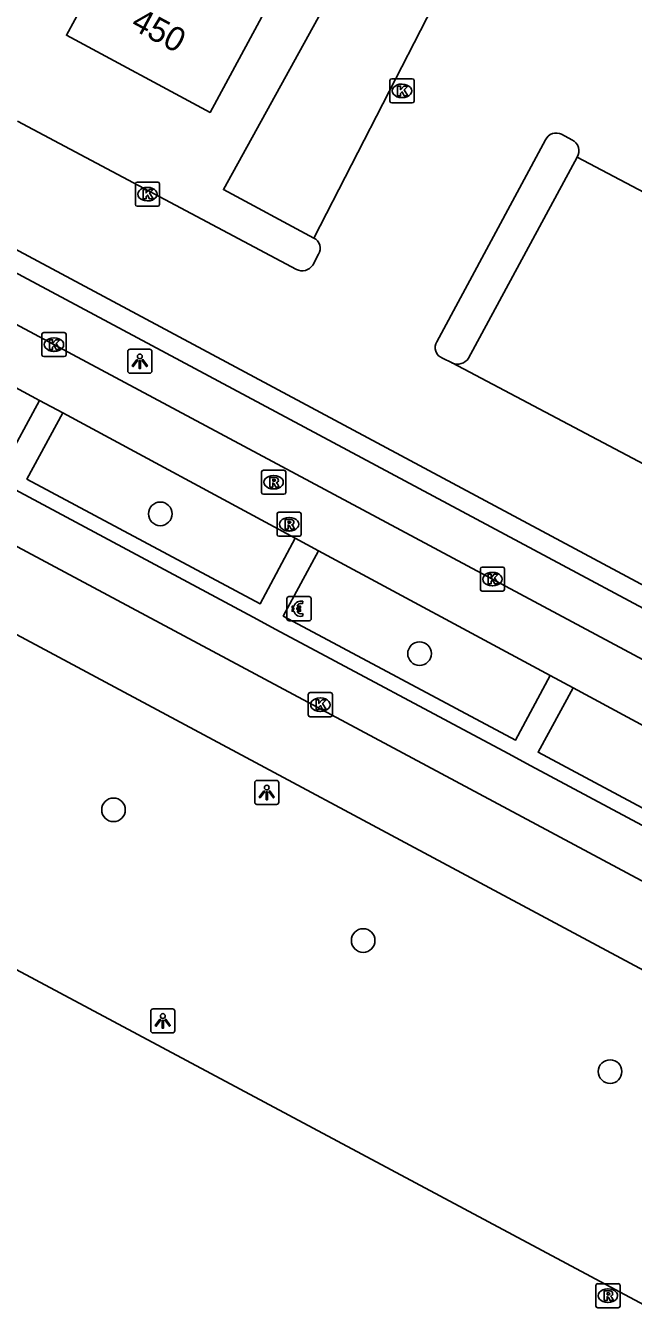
# Model space of a CAD drawing. Extents: x 159489 to 160304, y 383826 to 384530.
# Drawn here: x 159850 to 159875.2, y 383949.1 to 384002.3 of the extents above; entities that cross this region are included whole.
import ezdxf

# ---------------------------------------------------------------- set-up
doc = ezdxf.new("R2010")
doc.units = 0
for name, color, linetype in [('IMGEO_Betaalautomaat', 7, 'Continuous'), ('IMGEO_Boom', 7, 'Continuous'), ('IMGEO_Fietspad_gesloten', 7, 'Continuous'), ('IMGEO_Kolk', 7, 'Continuous'), ('IMGEO_Lichtpunt', 7, 'Continuous'), ('IMGEO_Pand', 7, 'Continuous'), ('IMGEO_Pand_nummerreeks', 7, 'Continuous'), ('IMGEO_Parkeervlak_open', 7, 'Continuous'), ('IMGEO_Rijbaan_lokaal_gesloten', 7, 'Continuous'), ('IMGEO_Rijbaan_lokaal_open', 7, 'Continuous'), ('IMGEO_Rioolput', 7, 'Continuous'), ('IMGEO_Voetpad_open', 7, 'Continuous')]:
    doc.layers.add(name, color=color, linetype=linetype)

msp = doc.modelspace()

# ---------------------------------------------------------------- linework, layer by layer
at = {"layer": 'IMGEO_Betaalautomaat'}
for p, q in [((159860.817, 383977.672), (159860.817, 383978.513)), ((159860.817, 383978.513), (159860.817, 383977.672)), ((159860.892, 383978.596), (159861.733, 383978.596)), ((159861.733, 383978.596), (159860.892, 383978.596)), ((159861.1, 383978.06), (159861.1, 383978.128)), ((159861.221, 383978.128), (159861.221, 383978.06)), ((159861.479, 383978.401), (159861.462, 383978.301)), ((159861.816, 383978.522), (159861.816, 383977.681)), ((159861.816, 383977.681), (159861.816, 383978.522)), ((159861.742, 383977.597), (159860.901, 383977.597)), ((159860.901, 383977.597), (159861.742, 383977.597)), ((159861.466, 383977.895), (159861.488, 383977.808))]:
    msp.add_line(p, q, dxfattribs=at)
for points in [[(159861.1, 383978.128), (159861.031, 383978.128), (159861.031, 383978.197), (159861.11, 383978.197)], [(159861.232, 383978.197), (159861.379, 383978.197), (159861.379, 383978.128), (159861.221, 383978.128)], [(159861.105, 383977.991), (159861.031, 383977.991), (159861.031, 383978.06), (159861.1, 383978.06)], [(159861.221, 383978.06), (159861.379, 383978.06), (159861.379, 383977.991), (159861.235, 383977.991)]]:
    msp.add_lwpolyline(points, dxfattribs=at)
for centre, radius, start, end in [((159860.895, 383978.519), 0.0779, 92.4484, 184.2845), ((159860.895, 383978.519), 0.0779, 92.4484, 184.2845), ((159861.393, 383978.121), 0.293, 73.014, 165.0139), ((159861.399, 383978.134), 0.179, 69.3236, 159.5683), ((159861.739, 383978.519), 0.0779, 2.4484, 94.2845), ((159861.739, 383978.519), 0.0779, 2.4484, 94.2845), ((159860.895, 383977.675), 0.0779, 182.4484, 274.2845), ((159860.895, 383977.675), 0.0779, 182.4484, 274.2845), ((159861.366, 383978.046), 0.267, 191.8096, 297.0389), ((159861.399, 383978.061), 0.179, 202.7625, 291.8693), ((159861.739, 383977.675), 0.0779, 272.4484, 4.2845), ((159861.739, 383977.675), 0.0779, 272.4484, 4.2845)]:
    msp.add_arc(centre, radius, start, end, dxfattribs=at)
at = {"layer": 'IMGEO_Boom'}
for centre in [(159855.571, 383982.025), (159866.307, 383976.234), (159853.632, 383969.76), (159863.972, 383964.345), (159874.198, 383958.915)]:
    msp.add_circle(centre, 0.489, dxfattribs=at)
at = {"layer": 'IMGEO_Fietspad_gesloten'}
for points in [[(159810.974, 384011.376), (159812.526, 384010.519), (159814.236, 384009.579), (159815.453, 384008.909), (159820.478, 384006.14), (159827.511, 384001.747), (159829.267, 384000.762), (159914.789, 383954.987)], [(159850.571, 383986.729), (159841.218, 383991.773)], [(159850.571, 383986.729), (159851.529, 383986.212)], [(159861.157, 383981.018), (159851.529, 383986.212)], [(159861.157, 383981.018), (159862.126, 383980.496)], [(159871.712, 383975.325), (159862.126, 383980.496)], [(159871.712, 383975.325), (159872.663, 383974.812)], [(159882.211, 383969.662), (159872.663, 383974.812)]]:
    msp.add_lwpolyline(points, dxfattribs=at)
at = {"layer": 'IMGEO_Kolk'}
for p, q in [((159865.079, 383999.128), (159865.079, 383999.98)), ((159865.154, 384000.054), (159866.006, 384000.054)), ((159866.08, 383999.98), (159866.08, 383999.128)), ((159865.567, 383999.834), (159865.592, 383999.834)), ((159866.006, 383999.054), (159865.154, 383999.054)), ((159865.59, 383999.274), (159865.565, 383999.274)), ((159854.537, 383994.847), (159854.537, 383995.699)), ((159854.612, 383995.773), (159855.464, 383995.773)), ((159855.538, 383995.699), (159855.538, 383994.847)), ((159855.025, 383995.553), (159855.05, 383995.553)), ((159855.464, 383994.773), (159854.612, 383994.773)), ((159855.048, 383994.993), (159855.023, 383994.993)), ((159850.667, 383988.614), (159850.667, 383989.466)), ((159850.742, 383989.54), (159851.594, 383989.54)), ((159851.155, 383989.32), (159851.18, 383989.32)), ((159851.668, 383989.466), (159851.668, 383988.614)), ((159851.178, 383988.76), (159851.153, 383988.76)), ((159851.594, 383988.54), (159850.742, 383988.54)), ((159868.825, 383978.895), (159868.825, 383979.747)), ((159868.9, 383979.821), (159869.752, 383979.821)), ((159869.826, 383979.747), (159869.826, 383978.895)), ((159869.313, 383979.601), (159869.338, 383979.601)), ((159869.752, 383978.821), (159868.9, 383978.821)), ((159869.336, 383979.041), (159869.311, 383979.041)), ((159861.698, 383973.691), (159861.698, 383974.543)), ((159861.773, 383974.617), (159862.625, 383974.617)), ((159862.699, 383974.543), (159862.699, 383973.691)), ((159862.186, 383974.397), (159862.211, 383974.397)), ((159862.625, 383973.617), (159861.773, 383973.617)), ((159862.209, 383973.837), (159862.184, 383973.837))]:
    msp.add_line(p, q, dxfattribs=at)
for points in [[(159865.079, 383999.128), (159865.079, 383999.98)], [(159865.154, 384000.054), (159866.006, 384000.054)], [(159866.08, 383999.98), (159866.08, 383999.128)], [(159865.4, 383999.754), (159865.523, 383999.754), (159865.523, 383999.603), (159865.653, 383999.754), (159865.817, 383999.754), (159865.671, 383999.603), (159865.824, 383999.354), (159865.672, 383999.354), (159865.587, 383999.518), (159865.523, 383999.451), (159865.523, 383999.354), (159865.4, 383999.354), (159865.4, 383999.754)], [(159866.006, 383999.054), (159865.154, 383999.054)], [(159854.537, 383994.847), (159854.537, 383995.699)], [(159854.612, 383995.773), (159855.464, 383995.773)], [(159855.538, 383995.699), (159855.538, 383994.847)], [(159854.858, 383995.473), (159854.981, 383995.473), (159854.981, 383995.322), (159855.111, 383995.473), (159855.275, 383995.473), (159855.129, 383995.322), (159855.282, 383995.073), (159855.13, 383995.073), (159855.045, 383995.237), (159854.981, 383995.17), (159854.981, 383995.073), (159854.858, 383995.073), (159854.858, 383995.473)], [(159855.464, 383994.773), (159854.612, 383994.773)], [(159850.667, 383988.614), (159850.667, 383989.466)], [(159850.742, 383989.54), (159851.594, 383989.54)], [(159851.668, 383989.466), (159851.668, 383988.614)], [(159850.988, 383989.24), (159851.111, 383989.24), (159851.111, 383989.089), (159851.241, 383989.24), (159851.405, 383989.24), (159851.259, 383989.089), (159851.412, 383988.84), (159851.26, 383988.84), (159851.175, 383989.004), (159851.111, 383988.937), (159851.111, 383988.84), (159850.988, 383988.84), (159850.988, 383989.24)], [(159851.594, 383988.54), (159850.742, 383988.54)], [(159868.825, 383978.895), (159868.825, 383979.747)], [(159868.9, 383979.821), (159869.752, 383979.821)], [(159869.826, 383979.747), (159869.826, 383978.895)], [(159869.146, 383979.521), (159869.269, 383979.521), (159869.269, 383979.37), (159869.399, 383979.521), (159869.563, 383979.521), (159869.417, 383979.37), (159869.57, 383979.121), (159869.418, 383979.121), (159869.333, 383979.285), (159869.269, 383979.218), (159869.269, 383979.121), (159869.146, 383979.121), (159869.146, 383979.521)], [(159869.752, 383978.821), (159868.9, 383978.821)], [(159861.698, 383973.691), (159861.698, 383974.543)], [(159861.773, 383974.617), (159862.625, 383974.617)], [(159862.699, 383974.543), (159862.699, 383973.691)], [(159862.019, 383974.317), (159862.142, 383974.317), (159862.142, 383974.166), (159862.272, 383974.317), (159862.436, 383974.317), (159862.29, 383974.166), (159862.443, 383973.917), (159862.291, 383973.917), (159862.206, 383974.081), (159862.142, 383974.014), (159862.142, 383973.917), (159862.019, 383973.917), (159862.019, 383974.317)], [(159862.625, 383973.617), (159861.773, 383973.617)]]:
    msp.add_lwpolyline(points, dxfattribs=at)
for centre, start, end in [((159865.156, 383999.978), 91.552, 178.448), ((159865.156, 383999.978), 91.552, 178.448), ((159866.004, 383999.978), 1.552, 88.448), ((159866.004, 383999.978), 1.552, 88.448), ((159865.156, 383999.13), 181.552, 268.448), ((159865.156, 383999.13), 181.552, 268.448), ((159866.004, 383999.13), 271.552, 358.448), ((159866.004, 383999.13), 271.552, 358.448), ((159854.614, 383995.697), 91.552, 178.448), ((159854.614, 383995.697), 91.552, 178.448), ((159855.462, 383995.697), 1.552, 88.448), ((159855.462, 383995.697), 1.552, 88.448), ((159854.614, 383994.849), 181.552, 268.448), ((159854.614, 383994.849), 181.552, 268.448), ((159855.462, 383994.849), 271.552, 358.448), ((159855.462, 383994.849), 271.552, 358.448), ((159850.744, 383989.464), 91.552, 178.448), ((159850.744, 383989.464), 91.552, 178.448), ((159851.592, 383989.464), 1.552, 88.448), ((159851.592, 383989.464), 1.552, 88.448), ((159850.744, 383988.616), 181.552, 268.448), ((159850.744, 383988.616), 181.552, 268.448), ((159851.592, 383988.616), 271.552, 358.448), ((159851.592, 383988.616), 271.552, 358.448), ((159868.902, 383979.745), 91.552, 178.448), ((159868.902, 383979.745), 91.552, 178.448), ((159869.75, 383979.745), 1.552, 88.448), ((159869.75, 383979.745), 1.552, 88.448), ((159868.902, 383978.897), 181.552, 268.448), ((159868.902, 383978.897), 181.552, 268.448), ((159869.75, 383978.897), 271.552, 358.448), ((159869.75, 383978.897), 271.552, 358.448), ((159861.775, 383974.541), 91.552, 178.448), ((159861.775, 383974.541), 91.552, 178.448), ((159862.623, 383974.541), 1.552, 88.448), ((159862.623, 383974.541), 1.552, 88.448), ((159861.775, 383973.693), 181.552, 268.448), ((159861.775, 383973.693), 181.552, 268.448), ((159862.623, 383973.693), 271.552, 358.448), ((159862.623, 383973.693), 271.552, 358.448)]:
    msp.add_arc(centre, 0.0765, start, end, dxfattribs=at)
for centre, major_axis, ratio, start_param, end_param in [((159865.566, 383999.554), (-0.387, 0.002), 0.722429, 4.712389, 7.853982), ((159865.591, 383999.554), (-0.39, 0.002), 0.717154, 1.570796, 4.712389), ((159855.024, 383995.273), (-0.387, 0.002), 0.722429, 4.712389, 7.853982), ((159855.049, 383995.273), (-0.39, 0.002), 0.717154, 1.570796, 4.712389), ((159851.154, 383989.04), (-0.387, 0.002), 0.722429, 4.712389, 7.853982), ((159851.179, 383989.04), (-0.39, 0.002), 0.717154, 1.570796, 4.712389), ((159869.312, 383979.321), (-0.387, 0.002), 0.722429, 4.712389, 7.853982), ((159869.337, 383979.321), (-0.39, 0.002), 0.717154, 1.570796, 4.712389), ((159862.185, 383974.117), (-0.387, 0.002), 0.722429, 4.712389, 7.853982), ((159862.21, 383974.117), (-0.39, 0.002), 0.717154, 1.570796, 4.712389)]:
    msp.add_ellipse(centre, major_axis=major_axis, ratio=ratio, start_param=start_param, end_param=end_param, dxfattribs=at)
at = {"layer": 'IMGEO_Lichtpunt'}
for p, q in [((159855.127, 383988.847), (159854.319, 383988.847)), ((159855.127, 383988.847), (159854.319, 383988.847)), ((159854.225, 383988.752), (159854.225, 383987.945)), ((159854.225, 383988.752), (159854.225, 383987.945)), ((159855.221, 383987.945), (159855.221, 383988.752)), ((159855.221, 383987.945), (159855.221, 383988.752)), ((159854.319, 383987.851), (159855.127, 383987.851)), ((159854.319, 383987.851), (159855.127, 383987.851)), ((159859.481, 383970.885), (159859.481, 383970.078)), ((159859.481, 383970.885), (159859.481, 383970.078)), ((159860.383, 383970.98), (159859.575, 383970.98)), ((159860.383, 383970.98), (159859.575, 383970.98)), ((159860.477, 383970.078), (159860.477, 383970.885)), ((159860.477, 383970.078), (159860.477, 383970.885)), ((159859.575, 383969.984), (159860.383, 383969.984)), ((159859.575, 383969.984), (159860.383, 383969.984)), ((159855.175, 383961.418), (159855.175, 383960.611)), ((159855.175, 383961.418), (159855.175, 383960.611)), ((159856.077, 383961.513), (159855.269, 383961.513)), ((159856.077, 383961.513), (159855.269, 383961.513)), ((159856.171, 383960.611), (159856.171, 383961.418)), ((159856.171, 383960.611), (159856.171, 383961.418)), ((159855.269, 383960.517), (159856.077, 383960.517)), ((159855.269, 383960.517), (159856.077, 383960.517))]:
    msp.add_line(p, q, dxfattribs=at)
for points in [[(159854.599, 383988.416), (159854.638, 383988.388), (159854.45, 383988.126), (159854.412, 383988.153), (159854.599, 383988.416)], [(159854.701, 383988.368), (159854.748, 383988.368), (159854.748, 383988.046), (159854.701, 383988.046), (159854.701, 383988.368)], [(159854.811, 383988.388), (159854.849, 383988.415), (159855.036, 383988.153), (159854.997, 383988.125), (159854.811, 383988.388)], [(159859.855, 383970.549), (159859.894, 383970.521), (159859.706, 383970.259), (159859.668, 383970.286), (159859.855, 383970.549)], [(159859.957, 383970.501), (159860.004, 383970.501), (159860.004, 383970.179), (159859.957, 383970.179), (159859.957, 383970.501)], [(159860.067, 383970.521), (159860.105, 383970.548), (159860.292, 383970.286), (159860.253, 383970.258), (159860.067, 383970.521)], [(159855.549, 383961.082), (159855.588, 383961.054), (159855.4, 383960.792), (159855.362, 383960.819), (159855.549, 383961.082)], [(159855.651, 383961.034), (159855.698, 383961.034), (159855.698, 383960.712), (159855.651, 383960.712), (159855.651, 383961.034)], [(159855.761, 383961.054), (159855.799, 383961.081), (159855.986, 383960.819), (159855.947, 383960.791), (159855.761, 383961.054)]]:
    msp.add_lwpolyline(points, dxfattribs=at)
for centre in [(159854.724, 383988.55), (159859.98, 383970.683), (159855.674, 383961.216)]:
    msp.add_circle(centre, 0.0994, dxfattribs=at)
for centre, start, end in [((159854.319, 383988.752), 90, 180), ((159854.319, 383988.752), 90, 180), ((159855.127, 383988.752), 0, 90), ((159855.127, 383988.752), 0, 90), ((159854.319, 383987.945), 180, 270), ((159854.319, 383987.945), 180, 270), ((159855.127, 383987.945), 270, 0), ((159855.127, 383987.945), 270, 360), ((159859.575, 383970.885), 90, 180), ((159859.575, 383970.885), 90, 180), ((159860.383, 383970.885), 0, 90), ((159860.383, 383970.885), 0, 90), ((159859.575, 383970.078), 180, 270), ((159859.575, 383970.078), 180, 270), ((159860.383, 383970.078), 270, 0), ((159860.383, 383970.078), 270, 360), ((159855.269, 383961.418), 90, 180), ((159855.269, 383961.418), 90, 180), ((159856.077, 383961.418), 0, 90), ((159856.077, 383961.418), 0, 90), ((159855.269, 383960.611), 180, 270), ((159855.269, 383960.611), 180, 270), ((159856.077, 383960.611), 270, 0), ((159856.077, 383960.611), 270, 360)]:
    msp.add_arc(centre, 0.0946, start, end, dxfattribs=at)
at = {"layer": 'IMGEO_Pand'}
msp.add_lwpolyline([(159861.9, 384006.569), (159855.968, 384009.769), (159854.991, 384007.958), (159853.233, 384008.905), (159850.977, 384004.724), (159852.72, 384003.785), (159851.682, 384001.859), (159857.633, 383998.662), (159861.9, 384006.569)], dxfattribs=at)
at = {"layer": 'IMGEO_Parkeervlak_open'}
msp.add_lwpolyline([(159868.337, 383988.475), (159872.835, 383996.806)], dxfattribs=at)
msp.add_arc((159867.88, 383988.774), 0.546, 245.5973, 326.7811, dxfattribs=at)
at = {"layer": 'IMGEO_Rijbaan_lokaal_gesloten'}
for points in [[(159888.304, 383959.967), (159818.858, 383997.143)], [(159840.297, 383982.009), (159884.338, 383958.42), (159887.722, 383956.4), (159898.39, 383949.315)], [(159893.167, 383939.859), (159842.117, 383967.14), (159837.777, 383969.747)]]:
    msp.add_lwpolyline(points, dxfattribs=at)
at = {"layer": 'IMGEO_Rijbaan_lokaal_open'}
for points in [[(159868.17, 384005.614), (159861.931, 383993.454)], [(159849.659, 383998.303), (159861.206, 383992.151)], [(159871.521, 383997.524), (159867.028, 383989.16)], [(159872.613, 383997.519), (159872.192, 383997.754)], [(159872.835, 383996.806), (159906.443, 383979.069)], [(159910.232, 383960.503), (159906.502, 383962.5), (159847.363, 383994.162)], [(159861.885, 383992.333), (159862.126, 383992.78)], [(159867.258, 383988.481), (159867.655, 383988.277)], [(159902.095, 383970.059), (159867.655, 383988.277)]]:
    msp.add_lwpolyline(points, dxfattribs=at)
for centre, radius, start, end in [((159871.968, 383997.313), 0.494, 63.0548, 154.7858), ((159872.415, 383997.066), 0.494, 328.1716, 66.4175), ((159861.73, 383993.031), 0.469, 327.7103, 64.5619), ((159861.44, 383992.637), 0.539, 244.302, 325.7079), ((159867.407, 383988.91), 0.454, 146.5775, 250.8484)]:
    msp.add_arc(centre, radius, start, end, dxfattribs=at)
at = {"layer": 'IMGEO_Rioolput'}
for p, q in [((159859.764, 383982.911), (159859.764, 383983.763)), ((159859.839, 383983.837), (159860.691, 383983.837)), ((159860.252, 383983.617), (159860.277, 383983.617)), ((159860.765, 383983.763), (159860.765, 383982.911)), ((159860.275, 383983.057), (159860.25, 383983.057)), ((159860.691, 383982.837), (159859.839, 383982.837)), ((159860.404, 383981.169), (159860.404, 383982.021)), ((159860.479, 383982.095), (159861.331, 383982.095)), ((159860.892, 383981.875), (159860.917, 383981.875)), ((159861.405, 383982.021), (159861.405, 383981.169)), ((159860.915, 383981.315), (159860.89, 383981.315)), ((159861.331, 383981.095), (159860.479, 383981.095)), ((159873.609, 383949.2), (159873.609, 383950.052)), ((159873.684, 383950.126), (159874.536, 383950.126)), ((159874.61, 383950.052), (159874.61, 383949.2)), ((159874.097, 383949.906), (159874.122, 383949.906)), ((159874.536, 383949.126), (159873.684, 383949.126)), ((159874.12, 383949.346), (159874.095, 383949.346))]:
    msp.add_line(p, q, dxfattribs=at)
for points in [[(159859.764, 383982.911), (159859.764, 383983.763)], [(159859.839, 383983.837), (159860.691, 383983.837)], [(159860.353, 383983.535), (159860.101, 383983.537), (159860.101, 383983.137)], [(159860.279, 383983.456), (159860.225, 383983.456), (159860.225, 383983.375)], [(159860.765, 383983.763), (159860.765, 383982.911)], [(159860.101, 383983.137), (159860.225, 383983.137), (159860.225, 383983.299), (159860.236, 383983.299)], [(159860.225, 383983.375), (159860.277, 383983.375)], [(159860.283, 383983.27), (159860.354, 383983.137), (159860.494, 383983.137), (159860.429, 383983.263)], [(159860.691, 383982.837), (159859.839, 383982.837)], [(159860.404, 383981.169), (159860.404, 383982.021)], [(159860.479, 383982.095), (159861.331, 383982.095)], [(159861.405, 383982.021), (159861.405, 383981.169)], [(159860.993, 383981.793), (159860.741, 383981.795), (159860.741, 383981.395)], [(159860.741, 383981.395), (159860.865, 383981.395), (159860.865, 383981.557), (159860.876, 383981.557)], [(159860.919, 383981.714), (159860.865, 383981.714), (159860.865, 383981.633)], [(159860.865, 383981.633), (159860.917, 383981.633)], [(159860.923, 383981.528), (159860.994, 383981.395), (159861.134, 383981.395), (159861.069, 383981.521)], [(159861.331, 383981.095), (159860.479, 383981.095)], [(159873.609, 383949.2), (159873.609, 383950.052)], [(159873.684, 383950.126), (159874.536, 383950.126)], [(159874.61, 383950.052), (159874.61, 383949.2)], [(159874.198, 383949.824), (159873.946, 383949.826), (159873.946, 383949.426)], [(159873.946, 383949.426), (159874.07, 383949.426), (159874.07, 383949.588), (159874.081, 383949.588)], [(159874.124, 383949.745), (159874.07, 383949.745), (159874.07, 383949.664)], [(159874.07, 383949.664), (159874.122, 383949.664)], [(159874.128, 383949.559), (159874.199, 383949.426), (159874.339, 383949.426), (159874.274, 383949.552)], [(159874.536, 383949.126), (159873.684, 383949.126)]]:
    msp.add_lwpolyline(points, dxfattribs=at)
for centre, radius, start, end in [((159859.841, 383983.761), 0.0765, 91.552, 178.448), ((159859.841, 383983.761), 0.0765, 91.552, 178.448), ((159860.285, 383983.36), 0.0964, 77.0061, 93.1865), ((159860.299, 383983.417), 0.0378, 276.6634, 79.6772), ((159860.352, 383983.425), 0.109, 350.3612, 89.416), ((159860.689, 383983.761), 0.0765, 1.552, 88.448), ((159860.689, 383983.761), 0.0765, 1.552, 88.448), ((159859.841, 383982.913), 0.0765, 181.552, 268.448), ((159859.841, 383982.913), 0.0765, 181.552, 268.448), ((159860.235, 383983.246), 0.0533, 26.0293, 88.6989), ((159860.261, 383983.564), 0.19, 274.7715, 282.9687), ((159860.35, 383983.425), 0.112, 277.5842, 350.9817), ((159860.334, 383983.21), 0.108, 29.5134, 73.7905), ((159860.689, 383982.913), 0.0765, 271.552, 358.448), ((159860.689, 383982.913), 0.0765, 271.552, 358.448), ((159860.481, 383982.019), 0.0765, 91.552, 178.448), ((159860.481, 383982.019), 0.0765, 91.552, 178.448), ((159861.329, 383982.019), 0.0765, 1.552, 88.448), ((159861.329, 383982.019), 0.0765, 1.552, 88.448), ((159860.875, 383981.504), 0.0533, 26.0293, 88.6989), ((159860.901, 383981.822), 0.19, 274.7715, 282.9687), ((159860.925, 383981.618), 0.0964, 77.0061, 93.1865), ((159860.939, 383981.675), 0.0378, 276.6634, 79.6772), ((159860.992, 383981.683), 0.109, 350.3612, 89.416), ((159860.99, 383981.683), 0.112, 277.5842, 350.9817), ((159860.974, 383981.468), 0.108, 29.5134, 73.7905), ((159860.481, 383981.171), 0.0765, 181.552, 268.448), ((159860.481, 383981.171), 0.0765, 181.552, 268.448), ((159861.329, 383981.171), 0.0765, 271.552, 358.448), ((159861.329, 383981.171), 0.0765, 271.552, 358.448), ((159873.686, 383950.05), 0.0765, 91.552, 178.448), ((159873.686, 383950.05), 0.0765, 91.552, 178.448), ((159874.534, 383950.05), 0.0765, 1.552, 88.448), ((159874.534, 383950.05), 0.0765, 1.552, 88.448), ((159874.08, 383949.535), 0.0533, 26.0293, 88.6989), ((159874.106, 383949.853), 0.19, 274.7715, 282.9687), ((159874.13, 383949.649), 0.0964, 77.0061, 93.1865), ((159874.144, 383949.706), 0.0378, 276.6634, 79.6772), ((159874.197, 383949.714), 0.109, 350.3612, 89.416), ((159874.195, 383949.714), 0.112, 277.5842, 350.9817), ((159874.179, 383949.499), 0.108, 29.5134, 73.7905), ((159873.686, 383949.202), 0.0765, 181.552, 268.448), ((159873.686, 383949.202), 0.0765, 181.552, 268.448), ((159874.534, 383949.202), 0.0765, 271.552, 358.448), ((159874.534, 383949.202), 0.0765, 271.552, 358.448)]:
    msp.add_arc(centre, radius, start, end, dxfattribs=at)
for centre, major_axis, ratio, start_param, end_param in [((159860.251, 383983.337), (-0.387, 0.002), 0.722429, 4.712389, 7.853982), ((159860.276, 383983.337), (-0.39, 0.002), 0.717154, 1.570796, 4.712389), ((159860.891, 383981.595), (-0.387, 0.002), 0.722429, 4.712389, 7.853982), ((159860.916, 383981.595), (-0.39, 0.002), 0.717154, 1.570796, 4.712389), ((159874.096, 383949.626), (-0.387, 0.002), 0.722429, 4.712389, 7.853982), ((159874.121, 383949.626), (-0.39, 0.002), 0.717154, 1.570796, 4.712389)]:
    msp.add_ellipse(centre, major_axis=major_axis, ratio=ratio, start_param=start_param, end_param=end_param, dxfattribs=at)
at = {"layer": 'IMGEO_Voetpad_open'}
for points in [[(159861.931, 383993.454), (159858.186, 383995.461), (159863.687, 384005.452), (159864.415, 384006.774)], [(159833.449, 384000.644), (159914.348, 383957.355)], [(159839.666, 383989.023), (159849.088, 383983.983), (159850.571, 383986.729)], [(159886.391, 383963.306), (159881.461, 383965.945), (159880.517, 383966.45), (159870.915, 383971.59), (159869.982, 383972.089), (159860.361, 383977.239), (159859.412, 383977.747), (159849.749, 383982.919), (159848.79, 383983.432), (159839.355, 383988.472)], [(159851.529, 383986.212), (159850.047, 383983.47), (159859.709, 383978.302), (159861.157, 383981.018)], [(159862.126, 383980.496), (159860.661, 383977.793), (159870.281, 383972.648), (159871.712, 383975.325)], [(159872.663, 383974.812), (159871.217, 383972.147), (159880.814, 383967.014), (159882.211, 383969.662)]]:
    msp.add_lwpolyline(points, dxfattribs=at)

# ---------------------------------------------------------------- texts
at = {"layer": 'IMGEO_Pand_nummerreeks'}
msp.add_text('450', height=1, rotation=331.7532, dxfattribs=at).set_placement((159854.299, 384002.156))

doc.saveas('drawing.dxf')
